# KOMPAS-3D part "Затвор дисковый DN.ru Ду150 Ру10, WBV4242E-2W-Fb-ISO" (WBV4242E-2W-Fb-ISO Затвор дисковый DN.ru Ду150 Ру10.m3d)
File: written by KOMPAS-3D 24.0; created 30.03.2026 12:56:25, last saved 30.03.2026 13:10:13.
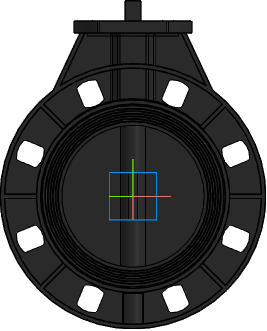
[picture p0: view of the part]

Document properties: Автор: R2D2; Полное имя файла: WBV4242E-2W-Fb-ISO Затвор дисковый DN.ru Ду150 Ру10.cdw

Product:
- Part/product: Затвор дисковый DN.ru Ду150 Ру10  | designation WBV4242E-2W-Fb-ISO
    Масса: 3.95
    Раздел спецификации: Прочие изделия
    Форматы листов документа: A2
    Примечание: D050-81209

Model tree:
1. Операция без истории:1

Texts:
  WBV4242E-2W-Fb-ISO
